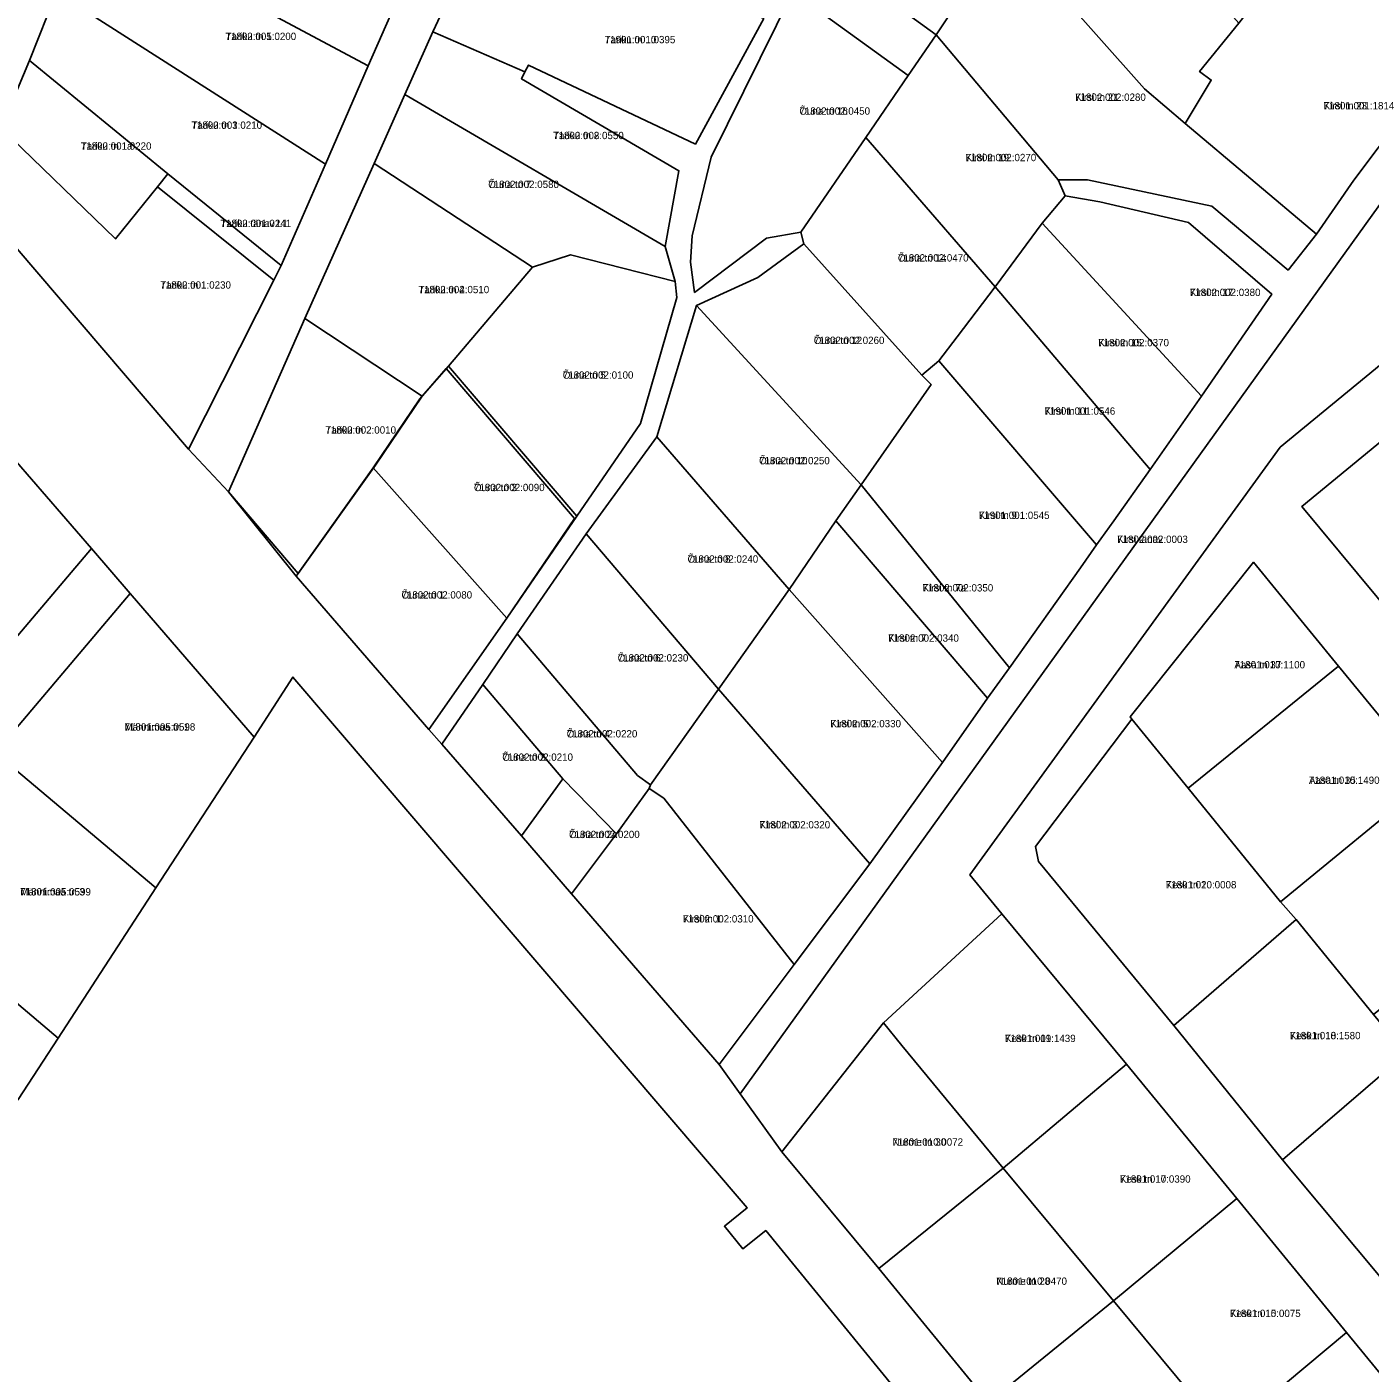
# Model space of a CAD drawing. Extents: x 529768 to 552006, y 6562269 to 6580975.
# Drawn here: x 537191.7 to 537467.3, y 6574194.8 to 6574471 of the extents above; entities that cross this region are included whole.
import ezdxf

# ---------------------------------------------------------------- set-up
doc = ezdxf.new("R2010")
doc.units = 0
for name, color, linetype in [('L_AADRESS', 7, 'Continuous'), ('PIIR', 7, 'Continuous'), ('TUNNUS', 7, 'Continuous')]:
    doc.layers.add(name, color=color, linetype=linetype)

msp = doc.modelspace()

# ---------------------------------------------------------------- linework, layer by layer
at = {"layer": 'PIIR'}
for points in [[(537176.64, 6574780.86), (537192.46, 6574780.83), (537456.9, 6574844.24), (537392.27, 6574743.64), (537376.22, 6574761.52), (537348.65, 6574793.39), (537302.74, 6574785.91), (537274.73, 6574780.91), (537253.3, 6574777.23), (537211.25, 6574769.95), (537221.41, 6574696.31), (537223.85, 6574678.91), (537211.39, 6574631.73), (537192.25, 6574575.13), (537223.08, 6574566.96), (537229.26, 6574557.38), (537225.37, 6574547.15), (537215.9, 6574524.17), (537210.09, 6574508.55), (537204.09, 6574493.83), (537197.75, 6574478.17), (537192.18, 6574464.15), (537186.43, 6574450.25)], [(537283.25, 6574487.75), (537274.96, 6574470.02), (537269.24, 6574457.17), (537262.94, 6574443), (537248.68, 6574411.21), (537233.07, 6574375.64), (537224.86, 6574384.41), (537242.33, 6574419.06), (537243.83, 6574422.06), (537252.92, 6574442.86), (537261.74, 6574463.02), (537270.12, 6574482.19)], [(537348.84, 6574478.2), (537332.1, 6574444.3), (537328.2, 6574428.17), (537327.86, 6574422.74), (537328.69, 6574416.55), (537343.48, 6574427.68), (537350.48, 6574428.88), (537351.12, 6574426.53), (537341.67, 6574419.59), (537329.08, 6574413.85), (537320.97, 6574386.9), (537306.43, 6574367.04), (537292.26, 6574346.49), (537285.22, 6574336.09), (537276.83, 6574323.83), (537274.19, 6574326.89), (537290.14, 6574349.71), (537304.5, 6574370.63), (537317.6, 6574389.66), (537325.07, 6574415.52), (537324.73, 6574418.77), (537322.63, 6574425.98), (537325.48, 6574441.52), (537293.2, 6574460.36), (537293.88, 6574461.81), (537294.58, 6574463.18), (537328.88, 6574446.97), (537342.87, 6574472.73)], [(537522.96, 6574478.54), (537539.43, 6574455.47), (537518.67, 6574442.15), (537448.89, 6574384.8), (537385.19, 6574297.04), (537391.74, 6574289.06), (537367.48, 6574266.71), (537346.58, 6574240.23), (537338.05, 6574252.13), (537488.95, 6574461.89), (537497.08, 6574478.43)], [(537488.95, 6574461.89), (537338.05, 6574252.13), (537333.74, 6574258.16), (537349.16, 6574278.67), (537364.66, 6574299.29), (537379.54, 6574320.1), (537388.79, 6574333.33), (537393.29, 6574339.49), (537407.89, 6574360.07), (537411.18, 6574364.73), (537414.72, 6574369.66), (537422.2, 6574380.19), (537432.71, 6574395.28), (537447.12, 6574416.2), (537430.03, 6574430.9), (537411.83, 6574435.13), (537404.76, 6574436.34), (537403.27, 6574439.63), (537409.31, 6574439.64), (537434.84, 6574434.24), (537450.49, 6574421.13), (537456.34, 6574428.53), (537464, 6574439.61), (537483.74, 6574465.85)], [(537485.04, 6574175.65), (537462.46, 6574203.17), (537439.95, 6574230.65), (537417.3, 6574258.22), (537391.74, 6574289.06), (537385.19, 6574297.04), (537448.89, 6574384.8), (537518.67, 6574442.15), (537526.58, 6574432.62), (537770.95, 6574137.8)], [(537180.73, 6574435.88), (537224.86, 6574384.41), (537233.07, 6574375.64), (537246.94, 6574358.35), (537274.19, 6574326.89), (537276.83, 6574323.83), (537293.16, 6574305.04), (537303.44, 6574293.12), (537333.74, 6574258.16), (537338.05, 6574252.13), (537346.58, 6574240.23), (537366.53, 6574216.28), (537388.98, 6574188.8)], [(537705.51, 6574191.94), (537686.51, 6574215.21), (537667.45, 6574238.35), (537648.32, 6574261.53), (537629.26, 6574284.54), (537610.16, 6574307.5), (537591.13, 6574330.78), (537572, 6574354.01), (537552.95, 6574377.28), (537533.81, 6574400.27), (537514.81, 6574423.43), (537484.09, 6574397.95), (537453.32, 6574372.65), (537472.43, 6574349.56), (537491.43, 6574326.43), (537510.45, 6574303.01), (537529.53, 6574279.73), (537548.85, 6574256.65), (537567.7, 6574233.55), (537586.91, 6574210.44), (537605.79, 6574187.21)], [(537406.38, 6574146.83), (537343.3, 6574224.07), (537338.62, 6574220.28), (537334.81, 6574224.93), (537339.48, 6574228.72), (537246.28, 6574337.64), (537238.29, 6574325.29), (537212.84, 6574354.8), (537204.91, 6574363.99), (537186.5, 6574385.35)], [(537177.64, 6574331.83), (537204.91, 6574363.99), (537212.84, 6574354.8), (537185.18, 6574322.09)], [(537594.3, 6574177.5), (537574.98, 6574200.96), (537556.1, 6574223.92), (537537.24, 6574247.03), (537517.79, 6574270.46), (537498.84, 6574293.5), (537479.78, 6574316.79), (537460.81, 6574339.88), (537443.38, 6574361.2), (537418.11, 6574329.45), (537418.41, 6574329.02), (537398.66, 6574302.87), (537399.29, 6574299.79), (537427.02, 6574266.11), (537449.34, 6574238.56), (537472.12, 6574211.28), (537494.41, 6574183.98)], [(537189.87, 6574250.96), (537198.07, 6574263.55), (537218.17, 6574294.4), (537238.29, 6574325.29), (537246.28, 6574337.64), (537339.48, 6574228.72), (537334.81, 6574224.93), (537338.62, 6574220.28), (537343.3, 6574224.07), (537406.38, 6574146.83), (537364.56, 6574090.16), (537339.57, 6574058.93), (537304.34, 6574012.42), (537259.15, 6573952.21), (537252.61, 6573957.01), (537199.14, 6573885.6), (537082.16, 6574038.28)]]:
    msp.add_lwpolyline(points, dxfattribs=at)
for points in [[(537378.29, 6574469.43), (537353.58, 6574487.32), (537365.49, 6574513.93), (537392.35, 6574490.59)], [(537421.03, 6574458.3), (537392.35, 6574490.59), (537406.41, 6574510.79), (537436.11, 6574476.64), (537440.36, 6574471.77), (537432.31, 6574461.86), (537434.71, 6574460.13), (537429.38, 6574451.24)], [(537210.09, 6574508.55), (537270.12, 6574482.19), (537261.74, 6574463.02), (537204.09, 6574493.83)], [(537204.09, 6574493.83), (537261.74, 6574463.02), (537252.92, 6574442.86), (537197.75, 6574478.17)], [(537274.96, 6574470.02), (537283.25, 6574487.75), (537301.83, 6574479.18), (537305.88, 6574488.4), (537342.87, 6574472.73), (537328.88, 6574446.97), (537294.58, 6574463.18), (537293.88, 6574461.81)], [(537403.27, 6574439.63), (537378.29, 6574469.43), (537392.35, 6574490.59), (537421.03, 6574458.3), (537429.38, 6574451.24), (537456.34, 6574428.53), (537450.49, 6574421.13), (537434.84, 6574434.24), (537409.31, 6574439.64)], [(537378.29, 6574469.43), (537372.53, 6574461.04), (537348.84, 6574478.2), (537353.58, 6574487.32)], [(537192.18, 6574464.15), (537197.75, 6574478.17), (537252.92, 6574442.86), (537243.83, 6574422.06), (537220.58, 6574440.85)], [(537343.48, 6574427.68), (537328.69, 6574416.55), (537327.86, 6574422.74), (537328.2, 6574428.17), (537332.1, 6574444.3), (537348.84, 6574478.2), (537372.53, 6574461.04), (537363.84, 6574448.36), (537350.48, 6574428.88)], [(537440.36, 6574471.77), (537445.63, 6574478.66), (537486.18, 6574475.14), (537483.74, 6574465.85), (537464, 6574439.61), (537456.34, 6574428.53), (537429.38, 6574451.24), (537434.71, 6574460.13), (537432.31, 6574461.86)], [(537269.24, 6574457.17), (537274.96, 6574470.02), (537293.88, 6574461.81), (537293.2, 6574460.36), (537325.48, 6574441.52), (537322.63, 6574425.98)], [(537372.53, 6574461.04), (537378.29, 6574469.43), (537403.27, 6574439.63), (537404.76, 6574436.34), (537400, 6574430.78), (537390.37, 6574417.67), (537363.84, 6574448.36)], [(537192.18, 6574464.15), (537220.58, 6574440.85), (537218.46, 6574438.23), (537209.84, 6574427.53), (537186.43, 6574450.25)], [(537262.94, 6574443), (537269.24, 6574457.17), (537322.63, 6574425.98), (537324.73, 6574418.77), (537303.23, 6574424.23), (537295.4, 6574421.73)], [(537242.33, 6574419.06), (537224.86, 6574384.41), (537180.73, 6574435.88), (537186.43, 6574450.25), (537209.84, 6574427.53), (537218.46, 6574438.23)], [(537350.48, 6574428.88), (537363.84, 6574448.36), (537390.37, 6574417.67), (537382.61, 6574407.46), (537378.81, 6574402.5), (537375.34, 6574399.57), (537351.12, 6574426.53)], [(537248.68, 6574411.21), (537262.94, 6574443), (537295.4, 6574421.73), (537278.2, 6574401.44), (537272.8, 6574395.25)], [(537220.58, 6574440.85), (537243.83, 6574422.06), (537242.33, 6574419.06), (537218.46, 6574438.23)], [(537404.76, 6574436.34), (537411.83, 6574435.13), (537430.03, 6574430.9), (537447.12, 6574416.2), (537432.71, 6574395.28), (537400, 6574430.78)], [(537400, 6574430.78), (537432.71, 6574395.28), (537422.2, 6574380.19), (537390.37, 6574417.67)], [(537341.67, 6574419.59), (537351.12, 6574426.53), (537375.34, 6574399.57), (537377.23, 6574397.69), (537362.88, 6574377.09), (537329.08, 6574413.85)], [(537278.2, 6574401.44), (537295.4, 6574421.73), (537303.23, 6574424.23), (537324.73, 6574418.77), (537325.07, 6574415.52), (537317.6, 6574389.66), (537304.5, 6574370.63)], [(537411.18, 6574364.73), (537378.81, 6574402.5), (537382.61, 6574407.46), (537390.37, 6574417.67), (537422.2, 6574380.19), (537414.72, 6574369.66)], [(537329.08, 6574413.85), (537362.88, 6574377.09), (537357.68, 6574369.7), (537348.07, 6574355.6), (537320.97, 6574386.9)], [(537247.32, 6574358.9), (537233.07, 6574375.64), (537248.68, 6574411.21), (537272.8, 6574395.25), (537263.19, 6574381.13)], [(537272.34, 6574394.71), (537277.72, 6574400.92), (537304.08, 6574370.14), (537290.14, 6574349.71), (537262.76, 6574380.58)], [(537393.29, 6574339.49), (537362.88, 6574377.09), (537377.23, 6574397.69), (537375.34, 6574399.57), (537378.81, 6574402.5), (537411.18, 6574364.73), (537407.89, 6574360.07)], [(537472.43, 6574349.56), (537453.32, 6574372.65), (537484.09, 6574397.95), (537504.31, 6574375.98)], [(537320.97, 6574386.9), (537348.07, 6574355.6), (537333.57, 6574335.12), (537306.43, 6574367.04)], [(537148.66, 6574352.81), (537186.5, 6574385.35), (537204.91, 6574363.99), (537177.64, 6574331.83), (537172.56, 6574329.53), (537167.43, 6574331.07)], [(537262.76, 6574380.58), (537290.14, 6574349.71), (537274.19, 6574326.89), (537246.94, 6574358.35)], [(537362.88, 6574377.09), (537393.29, 6574339.49), (537388.79, 6574333.33), (537357.68, 6574369.7)], [(537357.68, 6574369.7), (537388.79, 6574333.33), (537379.54, 6574320.1), (537348.07, 6574355.6)], [(537306.43, 6574367.04), (537333.57, 6574335.12), (537319.67, 6574315.51), (537317, 6574317.42), (537292.26, 6574346.49)], [(537443.38, 6574361.2), (537460.81, 6574339.88), (537429.96, 6574314.82), (537418.41, 6574329.02), (537418.11, 6574329.45)], [(537212.84, 6574354.8), (537238.29, 6574325.29), (537218.17, 6574294.4), (537185.18, 6574322.09)], [(537348.07, 6574355.6), (537379.54, 6574320.1), (537364.66, 6574299.29), (537333.57, 6574335.12)], [(537292.26, 6574346.49), (537317, 6574317.42), (537319.67, 6574315.51), (537319.37, 6574314.73), (537312.7, 6574305.44), (537301.66, 6574316.77), (537285.22, 6574336.09)], [(537460.81, 6574339.88), (537479.78, 6574316.79), (537448.9, 6574291.54), (537429.96, 6574314.82)], [(537285.22, 6574336.09), (537301.66, 6574316.77), (537293.16, 6574305.04), (537276.83, 6574323.83)], [(537319.37, 6574314.73), (537319.67, 6574315.51), (537333.57, 6574335.12), (537364.66, 6574299.29), (537349.16, 6574278.67), (537322.41, 6574312.75)], [(537399.29, 6574299.79), (537398.66, 6574302.87), (537418.41, 6574329.02), (537429.96, 6574314.82), (537448.9, 6574291.54), (537452.11, 6574287.88), (537427.02, 6574266.11)], [(537185.18, 6574322.09), (537218.17, 6574294.4), (537198.07, 6574263.55), (537161.63, 6574294.39)], [(537293.16, 6574305.04), (537301.66, 6574316.77), (537312.7, 6574305.44), (537303.44, 6574293.12)], [(537312.7, 6574305.44), (537319.37, 6574314.73), (537322.41, 6574312.75), (537349.16, 6574278.67), (537333.74, 6574258.16), (537303.44, 6574293.12)], [(537498.84, 6574293.5), (537468.01, 6574268.41), (537452.11, 6574287.88), (537448.9, 6574291.54), (537479.78, 6574316.79)], [(537161.63, 6574294.39), (537198.07, 6574263.55), (537189.87, 6574250.96), (537179.58, 6574238.8), (537141.8, 6574270.76)], [(537371.25, 6574262.01), (537367.48, 6574266.71), (537391.74, 6574289.06), (537417.3, 6574258.22), (537392, 6574236.87)], [(537452.11, 6574287.88), (537468.01, 6574268.41), (537474.68, 6574260.34), (537449.34, 6574238.56), (537427.02, 6574266.11)], [(537366.53, 6574216.28), (537346.58, 6574240.23), (537367.48, 6574266.71), (537371.25, 6574262.01), (537392, 6574236.87)], [(537449.34, 6574238.56), (537474.68, 6574260.34), (537487.02, 6574245.19), (537497.22, 6574232.79), (537472.12, 6574211.28)], [(537392, 6574236.87), (537417.3, 6574258.22), (537439.95, 6574230.65), (537414.69, 6574209.61)], [(537366.53, 6574216.28), (537392, 6574236.87), (537414.69, 6574209.61), (537388.98, 6574188.8)], [(537414.69, 6574209.61), (537439.95, 6574230.65), (537462.46, 6574203.17), (537437.45, 6574182.2)], [(537388.98, 6574188.8), (537414.69, 6574209.61), (537437.45, 6574182.2), (537411.58, 6574161.33)], [(537485.04, 6574175.65), (537459.79, 6574155.4), (537437.45, 6574182.2), (537462.46, 6574203.17)]]:
    msp.add_lwpolyline(points, close=True, dxfattribs=at)

# ---------------------------------------------------------------- texts
at = {"layer": 'L_AADRESS'}
for s, p in [('Tariku tn 5', (537232.44, 6574468.34)), ('Tariku tn 10', (537310.24, 6574467.68)), ('Kirsi tn 21', (537406.79, 6574455.86)), ('Kirsi tn 23', (537457.78, 6574454.11)), ('Õuna tn 16', (537350.2, 6574453.02)), ('Tariku tn 3', (537225.44, 6574450.12)), ('Tariku tn 1a', (537202.74, 6574445.84)), ('Tariku tn 8', (537299.66, 6574448)), ('Kirsi tn 19', (537384.3, 6574443.48)), ('Õuna tn 7', (537286.36, 6574437.97)), ('Tariku tänav L1', (537231.41, 6574429.96)), ('Õuna tn 14', (537370.42, 6574422.89)), ('Tariku tn 1', (537219.05, 6574417.33)), ('Tariku tn 4', (537272.04, 6574416.39)), ('Kirsi tn 17', (537430.32, 6574415.81)), ('Õuna tn 12', (537353.15, 6574405.97)), ('Kirsi tn 15', (537411.54, 6574405.5)), ('Õuna tn 5', (537301.64, 6574398.85)), ('Kirsi tn 11', (537400.51, 6574391.46)), ('Tariku tn 2', (537252.93, 6574387.58)), ('Õuna tn 10', (537341.93, 6574381.29)), ('Õuna tn 3', (537283.42, 6574375.78)), ('Kirsi tn 9', (537387.03, 6574370.07)), ('Kirsi tänav', (537415.41, 6574365.15)), ('Õuna tn 8', (537327.25, 6574361.1)), ('Kirsi tn 7a', (537375.48, 6574355.19)), ('Õuna tn 1', (537268.54, 6574353.74)), ('Kirsi tn 7', (537368.43, 6574344.88)), ('Õuna tn 6', (537312.91, 6574340.82)), ('Aasa tn 37', (537439.46, 6574339.41)), ('Männimaa tn 1', (537211.73, 6574326.65)), ('Kirsi tn 5', (537356.55, 6574327.33)), ('Õuna tn 4', (537302.45, 6574325.24)), ('Õuna tn 2', (537289.24, 6574320.45)), ('Aasa tn 35', (537454.76, 6574315.71)), ('Õuna tn 2a', (537302.93, 6574304.59)), ('Kirsi tn 3', (537342.01, 6574306.58)), ('Kesk tn 20', (537425.38, 6574294.27)), ('Männimaa tn 3', (537190.31, 6574292.82)), ('Kirsi tn 1', (537326.3, 6574287.27)), ('Kesk tn 18', (537450.85, 6574263.32)), ('Kesk tn 19', (537392.39, 6574262.74)), ('Nurme tn 30', (537369.29, 6574241.48)), ('Kesk tn 17', (537415.98, 6574233.89)), ('Nurme tn 28', (537390.61, 6574212.93)), ('Kesk tn 15', (537438.57, 6574206.32))]:
    msp.add_text(s, height=1.5, dxfattribs=at).set_placement(p)
at = {"layer": 'TUNNUS'}
for s, p in [('71802:001:0200', (537232.44, 6574468.34)), ('71901:001:0395', (537310.24, 6574467.68)), ('71802:002:0280', (537406.79, 6574455.86)), ('71801:001:1814', (537457.78, 6574454.11)), ('71802:002:0450', (537350.2, 6574453.02)), ('71802:001:0210', (537225.44, 6574450.12)), ('71802:001:0220', (537202.74, 6574445.84)), ('71802:002:0550', (537299.66, 6574448)), ('71802:002:0270', (537384.3, 6574443.48)), ('71802:002:0580', (537286.36, 6574437.97)), ('71802:001:0241', (537231.41, 6574429.96)), ('71802:002:0470', (537370.42, 6574422.89)), ('71802:001:0230', (537219.05, 6574417.33)), ('71802:002:0510', (537272.04, 6574416.39)), ('71802:002:0380', (537430.32, 6574415.81)), ('71802:002:0260', (537353.15, 6574405.97)), ('71802:002:0370', (537411.54, 6574405.5)), ('71802:002:0100', (537301.64, 6574398.85)), ('71901:001:0546', (537400.51, 6574391.46)), ('71802:002:0010', (537252.93, 6574387.58)), ('71802:002:0250', (537341.93, 6574381.29)), ('71802:002:0090', (537283.42, 6574375.78)), ('71901:001:0545', (537387.03, 6574370.07)), ('71802:002:0003', (537415.41, 6574365.15)), ('71802:002:0240', (537327.25, 6574361.1)), ('71802:002:0350', (537375.48, 6574355.19)), ('71802:002:0080', (537268.54, 6574353.74)), ('71802:002:0340', (537368.43, 6574344.88)), ('71802:002:0230', (537312.91, 6574340.82)), ('71801:010:1100', (537439.46, 6574339.41)), ('71801:005:0598', (537211.73, 6574326.65)), ('71802:002:0330', (537356.55, 6574327.33)), ('71802:002:0220', (537302.45, 6574325.24)), ('71802:002:0210', (537289.24, 6574320.45)), ('71801:010:1490', (537454.76, 6574315.71)), ('71802:002:0200', (537302.93, 6574304.59)), ('71802:002:0320', (537342.01, 6574306.58)), ('71801:010:0008', (537425.38, 6574294.27)), ('71801:005:0599', (537190.31, 6574292.82)), ('71802:002:0310', (537326.3, 6574287.27)), ('71801:010:1580', (537450.85, 6574263.32)), ('71801:001:1439', (537392.39, 6574262.74)), ('71801:010:0072', (537369.29, 6574241.48)), ('71801:010:0390', (537415.98, 6574233.89)), ('71801:010:0470', (537390.61, 6574212.93)), ('71801:010:0075', (537438.57, 6574206.32))]:
    msp.add_text(s, height=1.5, dxfattribs=at).set_placement(p)

doc.saveas('drawing.dxf')
